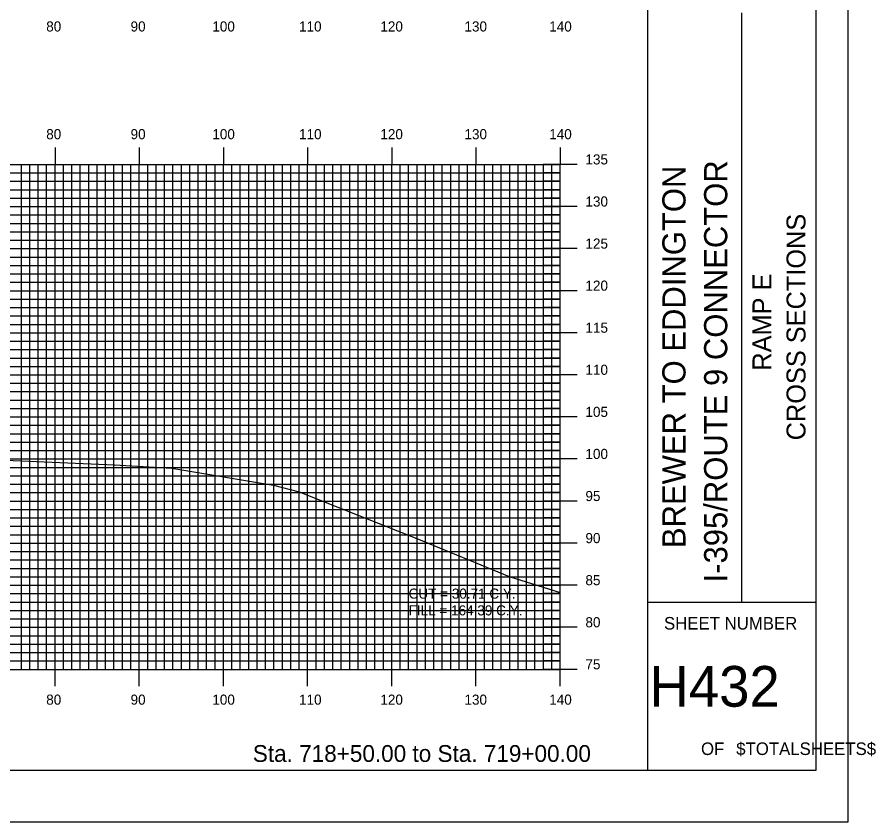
# Model space of a CAD drawing. Extents: x 857658 to 858001, y 364366 to 364586.
# Drawn here: x 857899.3 to 858001.3, y 364365.7 to 364461.3 of the extents above; entities that cross this region are included whole.
import ezdxf

# ---------------------------------------------------------------- set-up
doc = ezdxf.new("R2010")
doc.units = 0
for name, color, linetype in [('BORDER', 7, 'Continuous'), ('D_Text_Standard', 7, 'Continuous'), ('H_V ANNOTATION', 7, 'Continuous'), ('MAJOR', 7, 'Continuous'), ('MINOR', 7, 'Continuous'), ('PLOT BOUNDARY', 7, 'Continuous'), ('S_Roadway_Centerline', 7, 'Continuous')]:
    doc.layers.add(name, color=color, linetype=linetype)

msp = doc.modelspace()

# ---------------------------------------------------------------- linework, layer by layer
at = {"layer": 'BORDER'}
for p, q in [((857974.25, 364371.79), (857974.25, 364581.79)), ((857985.43, 364391.79), (857985.43, 364461.79)), ((857974.25, 364391.79), (857994.25, 364391.79))]:
    msp.add_line(p, q, dxfattribs=at)
msp.add_lwpolyline([(857674.25, 364371.79), (857994.25, 364371.79), (857994.25, 364581.79), (857674.25, 364581.79)], close=True, dxfattribs=at)
at = {"layer": 'MAJOR'}
for p, q in [((857903.85, 364445.79), (857903.85, 364443.79)), ((857913.85, 364445.79), (857913.85, 364443.79)), ((857923.85, 364445.79), (857923.85, 364443.79)), ((857933.85, 364445.79), (857933.85, 364443.79)), ((857943.85, 364445.79), (857943.85, 364443.79)), ((857953.85, 364445.79), (857953.85, 364443.79)), ((857963.85, 364445.79), (857963.85, 364443.79)), ((857683.85, 364443.79), (857963.85, 364443.79)), ((857683.85, 364443.79), (857963.85, 364443.79)), ((857903.85, 364383.79), (857903.85, 364443.79)), ((857913.85, 364383.79), (857913.85, 364443.79)), ((857923.85, 364383.79), (857923.85, 364443.79)), ((857933.85, 364383.79), (857933.85, 364443.79)), ((857943.85, 364383.79), (857943.85, 364443.79)), ((857953.85, 364383.79), (857953.85, 364443.79)), ((857965.85, 364443.79), (857961.84, 364443.79)), ((857963.85, 364383.79), (857963.85, 364443.79)), ((857963.85, 364383.79), (857963.85, 364443.79)), ((857683.85, 364438.79), (857963.85, 364438.79)), ((857965.85, 364438.79), (857961.84, 364438.79)), ((857683.85, 364433.79), (857963.85, 364433.79)), ((857965.85, 364433.79), (857961.84, 364433.79)), ((857683.85, 364428.79), (857963.85, 364428.79)), ((857965.85, 364428.79), (857961.84, 364428.79)), ((857683.85, 364423.79), (857963.85, 364423.79)), ((857965.85, 364423.79), (857961.84, 364423.79)), ((857683.85, 364418.79), (857963.85, 364418.79)), ((857965.85, 364418.79), (857961.84, 364418.79)), ((857683.85, 364413.79), (857963.85, 364413.79)), ((857965.85, 364413.79), (857961.84, 364413.79)), ((857683.85, 364408.79), (857963.85, 364408.79)), ((857965.85, 364408.79), (857961.84, 364408.79)), ((857683.85, 364403.79), (857963.85, 364403.79)), ((857965.85, 364403.79), (857961.84, 364403.79)), ((857683.85, 364398.79), (857963.85, 364398.79)), ((857965.85, 364398.79), (857961.84, 364398.79)), ((857683.85, 364393.79), (857963.85, 364393.79)), ((857965.85, 364393.79), (857961.84, 364393.79)), ((857683.85, 364388.79), (857963.85, 364388.79)), ((857965.85, 364388.79), (857961.84, 364388.79)), ((857683.85, 364383.79), (857963.85, 364383.79)), ((857683.85, 364383.79), (857963.85, 364383.79)), ((857903.85, 364381.78), (857903.85, 364383.79)), ((857913.85, 364381.78), (857913.85, 364383.79)), ((857923.85, 364381.78), (857923.85, 364383.79)), ((857933.85, 364381.78), (857933.85, 364383.79)), ((857943.85, 364381.78), (857943.85, 364383.79)), ((857953.85, 364381.78), (857953.85, 364383.79)), ((857965.85, 364383.79), (857961.84, 364383.79)), ((857963.85, 364381.78), (857963.85, 364383.79))]:
    msp.add_line(p, q, dxfattribs=at)
at = {"layer": 'MINOR'}
for p, q in [((857899.85, 364383.79), (857899.85, 364443.79)), ((857900.85, 364383.79), (857900.85, 364443.79)), ((857901.85, 364383.79), (857901.85, 364443.79)), ((857902.85, 364383.79), (857902.85, 364443.79)), ((857904.85, 364383.79), (857904.85, 364443.79)), ((857905.85, 364383.79), (857905.85, 364443.79)), ((857906.85, 364383.79), (857906.85, 364443.79)), ((857907.85, 364383.79), (857907.85, 364443.79)), ((857908.85, 364383.79), (857908.85, 364443.79)), ((857909.85, 364383.79), (857909.85, 364443.79)), ((857910.85, 364383.79), (857910.85, 364443.79)), ((857911.85, 364383.79), (857911.85, 364443.79)), ((857912.85, 364383.79), (857912.85, 364443.79)), ((857914.85, 364383.79), (857914.85, 364443.79)), ((857915.85, 364383.79), (857915.85, 364443.79)), ((857916.85, 364383.79), (857916.85, 364443.79)), ((857917.85, 364383.79), (857917.85, 364443.79)), ((857918.85, 364383.79), (857918.85, 364443.79)), ((857919.85, 364383.79), (857919.85, 364443.79)), ((857920.85, 364383.79), (857920.85, 364443.79)), ((857921.85, 364383.79), (857921.85, 364443.79)), ((857922.85, 364383.79), (857922.85, 364443.79)), ((857924.85, 364383.79), (857924.85, 364443.79)), ((857925.85, 364383.79), (857925.85, 364443.79)), ((857926.85, 364383.79), (857926.85, 364443.79)), ((857927.85, 364383.79), (857927.85, 364443.79)), ((857928.85, 364383.79), (857928.85, 364443.79)), ((857929.85, 364383.79), (857929.85, 364443.79)), ((857930.85, 364383.79), (857930.85, 364443.79)), ((857931.85, 364383.79), (857931.85, 364443.79)), ((857932.85, 364383.79), (857932.85, 364443.79)), ((857934.85, 364383.79), (857934.85, 364443.79)), ((857935.85, 364383.79), (857935.85, 364443.79)), ((857936.85, 364383.79), (857936.85, 364443.79)), ((857937.85, 364383.79), (857937.85, 364443.79)), ((857938.85, 364383.79), (857938.85, 364443.79)), ((857939.85, 364383.79), (857939.85, 364443.79)), ((857940.85, 364383.79), (857940.85, 364443.79)), ((857941.85, 364383.79), (857941.85, 364443.79)), ((857942.85, 364383.79), (857942.85, 364443.79)), ((857944.85, 364383.79), (857944.85, 364443.79)), ((857945.85, 364383.79), (857945.85, 364443.79)), ((857946.85, 364383.79), (857946.85, 364443.79)), ((857947.85, 364383.79), (857947.85, 364443.79)), ((857948.85, 364383.79), (857948.85, 364443.79)), ((857949.85, 364383.79), (857949.85, 364443.79)), ((857950.85, 364383.79), (857950.85, 364443.79)), ((857951.85, 364383.79), (857951.85, 364443.79)), ((857952.85, 364383.79), (857952.85, 364443.79)), ((857954.85, 364383.79), (857954.85, 364443.79)), ((857955.85, 364383.79), (857955.85, 364443.79)), ((857956.85, 364383.79), (857956.85, 364443.79)), ((857957.85, 364383.79), (857957.85, 364443.79)), ((857958.85, 364383.79), (857958.85, 364443.79)), ((857959.85, 364383.79), (857959.85, 364443.79)), ((857960.85, 364383.79), (857960.85, 364443.79)), ((857961.85, 364383.79), (857961.85, 364443.79)), ((857962.85, 364383.79), (857962.85, 364443.79)), ((857683.85, 364442.79), (857963.85, 364442.79)), ((857963.85, 364442.79), (857961.84, 364442.79)), ((857683.85, 364441.79), (857963.85, 364441.79)), ((857963.85, 364441.79), (857961.84, 364441.79)), ((857683.85, 364440.79), (857963.85, 364440.79)), ((857963.85, 364440.79), (857961.84, 364440.79)), ((857683.85, 364439.79), (857963.85, 364439.79)), ((857963.85, 364439.79), (857961.84, 364439.79)), ((857683.85, 364437.79), (857963.85, 364437.79)), ((857963.85, 364437.79), (857961.84, 364437.79)), ((857683.85, 364436.79), (857963.85, 364436.79)), ((857963.85, 364436.79), (857961.84, 364436.79)), ((857683.85, 364435.79), (857963.85, 364435.79)), ((857963.85, 364435.79), (857961.84, 364435.79)), ((857683.85, 364434.79), (857963.85, 364434.79)), ((857963.85, 364434.79), (857961.84, 364434.79)), ((857683.85, 364432.79), (857963.85, 364432.79)), ((857963.85, 364432.79), (857961.84, 364432.79)), ((857683.85, 364431.79), (857963.85, 364431.79)), ((857963.85, 364431.79), (857961.84, 364431.79)), ((857683.85, 364430.79), (857963.85, 364430.79)), ((857963.85, 364430.79), (857961.84, 364430.79)), ((857683.85, 364429.79), (857963.85, 364429.79)), ((857963.85, 364429.79), (857961.84, 364429.79)), ((857683.85, 364427.79), (857963.85, 364427.79)), ((857963.85, 364427.79), (857961.84, 364427.79)), ((857683.85, 364426.79), (857963.85, 364426.79)), ((857963.85, 364426.79), (857961.84, 364426.79)), ((857683.85, 364425.79), (857963.85, 364425.79)), ((857963.85, 364425.79), (857961.84, 364425.79)), ((857683.85, 364424.79), (857963.85, 364424.79)), ((857963.85, 364424.79), (857961.84, 364424.79)), ((857683.85, 364422.79), (857963.85, 364422.79)), ((857963.85, 364422.79), (857961.84, 364422.79)), ((857683.85, 364421.79), (857963.85, 364421.79)), ((857683.85, 364420.79), (857963.85, 364420.79)), ((857963.85, 364421.79), (857961.84, 364421.79)), ((857963.85, 364420.79), (857961.84, 364420.79)), ((857683.85, 364419.79), (857963.85, 364419.79)), ((857963.85, 364419.79), (857961.84, 364419.79)), ((857683.85, 364417.79), (857963.85, 364417.79)), ((857963.85, 364417.79), (857961.84, 364417.79)), ((857683.85, 364416.79), (857963.85, 364416.79)), ((857963.85, 364416.79), (857961.84, 364416.79)), ((857683.85, 364415.79), (857963.85, 364415.79)), ((857963.85, 364415.79), (857961.84, 364415.79)), ((857683.85, 364414.79), (857963.85, 364414.79)), ((857963.85, 364414.79), (857961.84, 364414.79)), ((857683.85, 364412.79), (857963.85, 364412.79)), ((857963.85, 364412.79), (857961.84, 364412.79)), ((857683.85, 364411.79), (857963.85, 364411.79)), ((857963.85, 364411.79), (857961.84, 364411.79)), ((857683.85, 364410.79), (857963.85, 364410.79)), ((857963.85, 364410.79), (857961.84, 364410.79)), ((857683.85, 364409.79), (857963.85, 364409.79)), ((857963.85, 364409.79), (857961.84, 364409.79)), ((857683.85, 364407.79), (857963.85, 364407.79)), ((857963.85, 364407.79), (857961.84, 364407.79)), ((857683.85, 364406.79), (857963.85, 364406.79)), ((857963.85, 364406.79), (857961.84, 364406.79)), ((857683.85, 364405.79), (857963.85, 364405.79)), ((857963.85, 364405.79), (857961.84, 364405.79)), ((857683.85, 364404.79), (857963.85, 364404.79)), ((857963.85, 364404.79), (857961.84, 364404.79)), ((857683.85, 364402.79), (857963.85, 364402.79)), ((857963.85, 364402.79), (857961.84, 364402.79)), ((857683.85, 364401.79), (857963.85, 364401.79)), ((857963.85, 364401.79), (857961.84, 364401.79)), ((857683.85, 364400.79), (857963.85, 364400.79)), ((857963.85, 364400.79), (857961.84, 364400.79)), ((857683.85, 364399.79), (857963.85, 364399.79)), ((857963.85, 364399.79), (857961.84, 364399.79)), ((857683.85, 364397.79), (857963.85, 364397.79)), ((857963.85, 364397.79), (857961.84, 364397.79)), ((857683.85, 364396.79), (857963.85, 364396.79)), ((857963.85, 364396.79), (857961.84, 364396.79)), ((857683.85, 364395.79), (857963.85, 364395.79)), ((857963.85, 364395.79), (857961.84, 364395.79)), ((857683.85, 364394.79), (857963.85, 364394.79)), ((857963.85, 364394.79), (857961.84, 364394.79)), ((857683.85, 364392.79), (857963.85, 364392.79)), ((857963.85, 364392.79), (857961.84, 364392.79)), ((857683.85, 364391.79), (857963.85, 364391.79)), ((857963.85, 364391.79), (857961.84, 364391.79)), ((857683.85, 364390.79), (857963.85, 364390.79)), ((857963.85, 364390.79), (857961.84, 364390.79)), ((857683.85, 364389.79), (857963.85, 364389.79)), ((857963.85, 364389.79), (857961.84, 364389.79)), ((857683.85, 364387.79), (857963.85, 364387.79)), ((857963.85, 364387.79), (857961.84, 364387.79)), ((857683.85, 364386.79), (857963.85, 364386.79)), ((857963.85, 364386.79), (857961.84, 364386.79)), ((857683.85, 364385.79), (857963.85, 364385.79)), ((857963.85, 364385.79), (857961.84, 364385.79)), ((857683.85, 364384.79), (857963.85, 364384.79)), ((857963.85, 364384.79), (857961.84, 364384.79))]:
    msp.add_line(p, q, dxfattribs=at)
at = {"layer": 'PLOT BOUNDARY'}
msp.add_lwpolyline([(857658.06, 364365.67), (857998.06, 364365.67), (857998.06, 364585.67), (857658.06, 364585.67)], close=True, dxfattribs=at)
at = {"layer": 'S_Roadway_Centerline'}
msp.add_lwpolyline([(857896.96, 364408.7), (857910.89, 364408.09), (857917.72, 364407.69), (857929.81, 364405.67), (857932.84, 364404.88), (857946.82, 364399.33), (857957.78, 364394.82), (857963.85, 364392.91)], dxfattribs=at)

# ---------------------------------------------------------------- texts
at = {"layer": 'BORDER'}
for s, height, p in [('BREWER TO EDDINGTON', 2.7557, (857978.74, 364398.2)), ('I-395/ROUTE 9 CONNECTOR', 2.7557, (857983.7, 364394.12)), ('CROSS SECTIONS', 2.25, (857992.99, 364411.01)), ('RAMP E', 2.25, (857988.94, 364419.29))]:
    msp.add_text(s, height=height, rotation=90, dxfattribs=at).set_placement(p)
for s, height, p in [('SHEET NUMBER', 1.4905, (857976.18, 364388.52)), ('H432', 4.839, (857974.46, 364379.35)), ('OF', 1.491, (857980.58, 364373.61)), ('$TOTALSHEETS$', 1.4905, (857984.76, 364373.61))]:
    msp.add_text(s, height=height, dxfattribs=at).set_placement(p)
at = {"layer": 'D_Text_Standard'}
for s, p in [('CUT = 30.71 C.Y.', (857945.85, 364392.19)), ('FILL = 164.39 C.Y.', (857945.85, 364390.2))]:
    msp.add_text(s, height=1.2, dxfattribs=at).set_placement(p)
at = {"layer": 'H_V ANNOTATION'}
for s, height, p in [('80', 1.2, (857902.8, 364459.59)), ('90', 1.2, (857912.82, 364459.59)), ('100', 1.2, (857922.53, 364459.59)), ('110', 1.2, (857932.83, 364459.59)), ('120', 1.2, (857942.49, 364459.59)), ('130', 1.2, (857952.48, 364459.59)), ('140', 1.2, (857962.55, 364459.59)), ('80', 1.2, (857902.8, 364446.79)), ('90', 1.2, (857912.82, 364446.79)), ('100', 1.2, (857922.53, 364446.79)), ('110', 1.2, (857932.83, 364446.79)), ('120', 1.2, (857942.49, 364446.79)), ('130', 1.2, (857952.48, 364446.79)), ('140', 1.2, (857962.55, 364446.79)), ('135', 1.2, (857966.85, 364443.79)), ('130', 1.2, (857966.85, 364438.79)), ('125', 1.2, (857966.85, 364433.79)), ('120', 1.2, (857966.85, 364428.79)), ('115', 1.2, (857966.85, 364423.79)), ('110', 1.2, (857966.85, 364418.79)), ('105', 1.2, (857966.85, 364413.79)), ('100', 1.2, (857966.85, 364408.79)), ('95', 1.2, (857966.85, 364403.79)), ('90', 1.2, (857966.85, 364398.79)), ('85', 1.2, (857966.85, 364393.79)), ('80', 1.2, (857966.85, 364388.79)), ('75', 1.2, (857966.85, 364383.79)), ('80', 1.2, (857902.8, 364379.59)), ('90', 1.2, (857912.82, 364379.59)), ('100', 1.2, (857922.53, 364379.59)), ('110', 1.2, (857932.83, 364379.59)), ('120', 1.2, (857942.49, 364379.59)), ('130', 1.2, (857952.48, 364379.59)), ('140', 1.2, (857962.55, 364379.59)), ('Sta. 718+50.00 to Sta. 719+00.00', 2.0004, (857927.34, 364372.79))]:
    msp.add_text(s, height=height, dxfattribs=at).set_placement(p)

doc.saveas('drawing.dxf')
